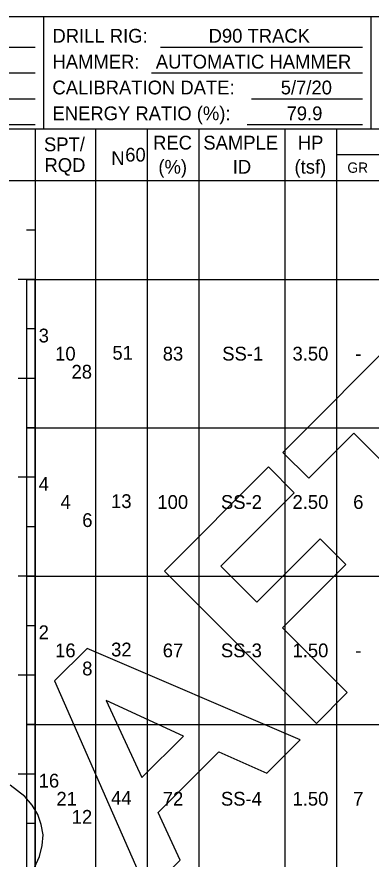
# Model space of a CAD drawing. Extents: x -0.01 to 0.83, y -0.63 to 1.27.
# Drawn here: x 0.4036 to 0.5751, y 0.8677 to 1.275 of the extents above; entities that cross this region are included whole.
import ezdxf

# ---------------------------------------------------------------- set-up
doc = ezdxf.new("R2010")
doc.units = 0

# ---------------------------------------------------------------- blocks, each defined once
blk = doc.blocks.new('DGRFC!DRAFT - ARIAL')
blk.add_lwpolyline([(0.13537, 0.03776), (0.1398, 0.03946), (0.14354, 0.04167), (0.14668, 0.04439), (0.14906, 0.0477), (0.15085, 0.05136), (0.15187, 0.05544), (0.15221, 0.05986), (0.15128, 0.06692)])
for points in [[(0.15952, 0), (0.1773, 0), (0.18427, 0.01896), (0.21752, 0.01896), (0.22474, 0), (0.24311, 0), (0.20978, 0.08333), (0.19192, 0.08333)], [(0.25204, 0), (0.26888, 0), (0.26888, 0.03546), (0.30349, 0.03546), (0.30349, 0.04949), (0.26888, 0.04949), (0.26888, 0.06922), (0.30901, 0.06922), (0.30901, 0.08333), (0.25204, 0.08333)], [(0.34167, 0), (0.3585, 0), (0.3585, 0.06922), (0.38308, 0.06922), (0.38308, 0.08333), (0.31701, 0.08333), (0.31701, 0.06922), (0.34167, 0.06922)], [(0.18937, 0.03299), (0.21216, 0.03299), (0.20068, 0.06386)]]:
    blk.add_lwpolyline(points, close=True)

msp = doc.modelspace()

# ---------------------------------------------------------------- linework, layer by layer
for points in [[(0, 0), (0.83333, 0), (0.83333, 1.275), (0, 1.275)], [(0, 0), (0.83333, 0), (0.83333, 1.275), (0, 1.275)], [(0, 0), (0.83333, 0), (0.83333, 1.275), (0, 1.275)], [(0, 0), (0.83333, 0), (0.83333, 1.275), (0, 1.275)], [(0, 0), (0.83333, 0), (0.83333, 1.275), (0, 1.275)], [(0.40833, 1.07625), (0.4125, 1.07625), (0.4125, 1.148), (0.40833, 1.148)], [(0.40833, 1.0045), (0.4125, 1.0045), (0.4125, 1.07625), (0.40833, 1.07625)], [(0.40833, 0.93275), (0.4125, 0.93275), (0.4125, 1.0045), (0.40833, 1.0045)], [(0.40833, 0.861), (0.4125, 0.861), (0.4125, 0.93275), (0.40833, 0.93275)]]:
    msp.add_lwpolyline(points, close=True)
for points in [[(0.41667, 1.22083), (0.41667, 1.275)], [(0.575, 1.22083), (0.575, 1.275)], [(0.32667, 1.26041), (0.4125, 1.26041)], [(0.47305, 1.26041), (0.57083, 1.26041)], [(0.31944, 1.24791), (0.4125, 1.24791)], [(0.46875, 1.24791), (0.57083, 1.24791)], [(0.28403, 1.23541), (0.4125, 1.23541)], [(0.51722, 1.23541), (0.57083, 1.23541)], [(0.2893, 1.22291), (0.4125, 1.22291)], [(0.51514, 1.22291), (0.57083, 1.22291)], [(0, 1.22083), (0.83333, 1.22083)], [(0, 1.22083), (0.83333, 1.22083)], [(0, 1.22083), (0.83333, 1.22083)], [(0, 1.22083), (0.83333, 1.22083)], [(0, 1.22083), (0.83333, 1.22083)], [(0.4125, 1.22083), (0.4125, -0.62183)], [(0.4125, 1.22083), (0.4125, -0.62183)], [(0.44167, 1.22083), (0.44167, -0.62183)], [(0.46667, 1.22083), (0.46667, -0.62183)], [(0.49167, 1.22083), (0.49167, -0.62183)], [(0.53333, 1.22083), (0.53333, -0.62183)], [(0.55833, 1.22083), (0.55833, -0.62183)], [(0.725, 1.20833), (0.55833, 1.20833)], [(0, 1.19583), (0.83333, 1.19583)], [(0, 1.19583), (0.83333, 1.19583)], [(0, 1.19583), (0.83333, 1.19583)], [(0, 1.19583), (0.83333, 1.19583)], [(0, 1.19583), (0.83333, 1.19583)], [(0.4125, 1.17191), (0.40833, 1.17191)], [(0.4125, 1.148), (0.40417, 1.148)], [(0.40833, 1.148), (0.40833, 1.07625)], [(0.40833, 1.148), (0.4125, 1.148)], [(0.4125, 1.148), (0.40833, 1.148)], [(0.4125, 1.148), (0.44167, 1.148)], [(0.44167, 1.148), (0.46667, 1.148)], [(0.46667, 1.148), (0.49167, 1.148)], [(0.49167, 1.148), (0.53333, 1.148)], [(0.53333, 1.148), (0.55833, 1.148)], [(0.55833, 1.148), (0.57917, 1.148)], [(0.4125, 1.12408), (0.40833, 1.12408)], [(0.4125, 1.10016), (0.40417, 1.10016)], [(0.4125, 1.10016), (0.40833, 1.10016)], [(0.40833, 1.07625), (0.4125, 1.07625)], [(0.40833, 1.07625), (0.40833, 1.0045)], [(0.40833, 1.07625), (0.4125, 1.07625)], [(0.4125, 1.07625), (0.40833, 1.07625)], [(0.4125, 1.07625), (0.44167, 1.07625)], [(0.44167, 1.07625), (0.46667, 1.07625)], [(0.46667, 1.07625), (0.49167, 1.07625)], [(0.49167, 1.07625), (0.53333, 1.07625)], [(0.53333, 1.07625), (0.55833, 1.07625)], [(0.55833, 1.07625), (0.57917, 1.07625)], [(0.4125, 1.05233), (0.40417, 1.05233)], [(0.4125, 1.05233), (0.40833, 1.05233)], [(0.4125, 1.02841), (0.40833, 1.02841)], [(0.4125, 1.0045), (0.40417, 1.0045)], [(0.40833, 1.0045), (0.4125, 1.0045)], [(0.40833, 1.0045), (0.40833, 0.93275)], [(0.40833, 1.0045), (0.4125, 1.0045)], [(0.4125, 1.0045), (0.40833, 1.0045)], [(0.4125, 1.0045), (0.44167, 1.0045)], [(0.44167, 1.0045), (0.46667, 1.0045)], [(0.46667, 1.0045), (0.49167, 1.0045)], [(0.49167, 1.0045), (0.53333, 1.0045)], [(0.53333, 1.0045), (0.55833, 1.0045)], [(0.55833, 1.0045), (0.57917, 1.0045)], [(0.4125, 0.98058), (0.40833, 0.98058)], [(0.4125, 0.95666), (0.40417, 0.95666)], [(0.4125, 0.95666), (0.40833, 0.95666)], [(0.40833, 0.93275), (0.4125, 0.93275)], [(0.40833, 0.93275), (0.40833, 0.861)], [(0.40833, 0.93275), (0.4125, 0.93275)], [(0.4125, 0.93275), (0.40833, 0.93275)], [(0.4125, 0.93275), (0.44167, 0.93275)], [(0.44167, 0.93275), (0.46667, 0.93275)], [(0.46667, 0.93275), (0.49167, 0.93275)], [(0.49167, 0.93275), (0.53333, 0.93275)], [(0.53333, 0.93275), (0.55833, 0.93275)], [(0.55833, 0.93275), (0.57917, 0.93275)], [(0.4125, 0.90883), (0.40417, 0.90883)], [(0.4125, 0.90883), (0.40833, 0.90883)], [(0.4125, 0.88491), (0.40833, 0.88491)]]:
    msp.add_lwpolyline(points)

# ---------------------------------------------------------------- block references
at = {"xscale": 1.25, "yscale": 1.25, "rotation": 45}
msp.add_blockref('DGRFC!DRAFT - ARIAL', (0.32586, 0.71054), dxfattribs=at)

# ---------------------------------------------------------------- texts
for s, height, p in [('DRILL RIG:', 0.006667, (0.42083, 1.2625)), ('D90 TRACK', 0.006667, (0.49641, 1.2625)), ('HAMMER:', 0.006667, (0.42083, 1.25)), ('AUTOMATIC HAMMER', 0.0066667, (0.47086, 1.25)), ('CALIBRATION DATE:', 0.0066667, (0.42083, 1.2375)), ('5/7/20', 0.006667, (0.53131, 1.2375)), ('ENERGY RATIO (%):', 0.0066667, (0.42083, 1.225)), ('79.9', 0.006667, (0.53413, 1.225)), ('SPT/', 0.006667, (0.41673, 1.21)), ('REC', 0.006667, (0.46952, 1.21083)), ('SAMPLE', 0.006667, (0.49385, 1.21083)), ('HP', 0.006667, (0.53956, 1.21083)), ('N', 0.00667, (0.44932, 1.20333)), ('60', 0.006667, (0.45604, 1.205)), ('RQD', 0.006667, (0.41698, 1.2)), ('(%)', 0.006667, (0.47209, 1.19916)), ('ID', 0.006667, (0.50809, 1.19916)), ('(tsf)', 0.006667, (0.53798, 1.19916)), ('GR', 0.005, (0.56356, 1.19958)), ('3', 0.00667, (0.41417, 1.11754)), ('10', 0.006667, (0.42213, 1.10879)), ('51', 0.006667, (0.44984, 1.10921)), ('83', 0.006667, (0.4742, 1.10879)), ('SS-1', 0.006667, (0.503, 1.10879)), ('3.50', 0.006667, (0.537, 1.10879)), ('-', 0.00667, (0.56734, 1.10879)), ('28', 0.006667, (0.43006, 1.10004)), ('4', 0.00667, (0.41417, 1.04579)), ('4', 0.00667, (0.42472, 1.03704)), ('13', 0.006667, (0.4492, 1.03746)), ('100', 0.006667, (0.47162, 1.03704)), ('SS-2', 0.006667, (0.50239, 1.03704)), ('2.50', 0.006667, (0.537, 1.03704)), ('6', 0.00667, (0.56637, 1.03704)), ('6', 0.00667, (0.43524, 1.02829)), ('2', 0.00667, (0.41417, 0.97404)), ('16', 0.006667, (0.42212, 0.96529)), ('32', 0.006667, (0.44923, 0.96571)), ('67', 0.006667, (0.4742, 0.96529)), ('SS-3', 0.006667, (0.50236, 0.96529)), ('1.50', 0.006667, (0.537, 0.96529)), ('-', 0.00667, (0.56734, 0.96529)), ('8', 0.00667, (0.43523, 0.95654)), ('16', 0.006667, (0.41417, 0.90229)), ('21', 0.006667, (0.42276, 0.89354)), ('44', 0.006667, (0.44921, 0.89396)), ('72', 0.006667, (0.47423, 0.89354)), ('SS-4', 0.006667, (0.50237, 0.89354)), ('1.50', 0.006667, (0.537, 0.89354)), ('7', 0.00667, (0.56637, 0.89354)), ('12', 0.006667, (0.43014, 0.88479))]:
    msp.add_text(s, height=height).set_placement(p)

doc.saveas('drawing.dxf')
